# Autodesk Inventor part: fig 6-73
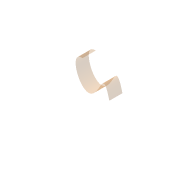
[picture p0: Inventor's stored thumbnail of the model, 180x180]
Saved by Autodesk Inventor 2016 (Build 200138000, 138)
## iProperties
Shininess: 64.0
Length Units: 11269
Angle Units: 11279
Time Units: 11290
Mass Units: 11283
Length Display Precision: 3
Angle Display Precision: 2
Compacted: True
Part Number: fig 6-73
Document SubType Name: Modeling
Created: 2002-12
Designer: deepak
Density: 1 g/cm^3
Material: Generic
Appearance: Default
Density: 0.0
Volumn: 0.0
Area: 0.0
PropertySet Name: Model Information
Control State: 0
Master: False
Checked Out: False
Author: deepak
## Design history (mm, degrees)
sketch "Sketch1"
  geometry: 5 further points
  constraints: 5 other
extrude_surface "ExtrusionSrf1" sketch "Sketch1" dims "d0" = 20, "d1" = 0
body "Srf1"
